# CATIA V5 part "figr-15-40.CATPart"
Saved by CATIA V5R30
Part number: Part1
Bounding box of the stored display mesh (mm): x -55.204 to 69.266, y -33.79 to 44.107, z 0 to 118.408
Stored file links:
  D:\PROJECTS\CATIA V56R 2020\Resources\Parts File\c15_catia_v5_6r2020_prt\figr-15-40.CATPart
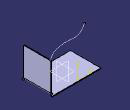
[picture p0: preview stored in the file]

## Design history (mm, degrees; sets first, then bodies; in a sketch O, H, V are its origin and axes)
SheetMetalParameters1: Thickness 2, BendRadius 4, KFactor 0.400515 {= log(min(100,max(20*SheetMetalParameters1.BendRadius,SheetMetalParameters1.Thickness)/SheetMetalParameters1.Thickness))/log(100)/2}, ReliefRadialLength 1, ReliefAxialLength 2, MinimumBendRadius 0
Body1 (main body)
  Sketch1 on xy-plane, origin (0, 0, 0), H (1, 0, 0), V (0, 1, 0)
    line L1 (-55.2037, 44.1067) -> (69.266, 44.1067)
    line L2 (69.266, 44.1067) -> (69.266, -33.7896)
    line L3 (69.266, -33.7896) -> (-55.2037, -33.7896)
    line L4 (-55.2037, -33.7896) -> (-55.2037, 44.1067)
    horizontal: L1 H, L3 H
    vertical: L2 V, L4 V
  Wall1: Thickness 2, Profile Sketch1, OffsetValue 0
  d_NewWallOnEdge1: NewWallOnEdge_Length 77.8964, NewWallOnEdge_HeightLimitOffset 0, NewWallOnEdge_WidthOffset1 -4, NewWallOnEdge_WidthOffset2 -4, NewWallOnEdge_Angle 90, NewWallOnEdge_BendRadiusValue 4 {= SheetMetalParameters1.BendRadius}, NewWallOnEdge_BendTable SheetMetalParameters1, NewWallOnEdge_Edge edge [face of Wall1 | face of Wall1], NewWallOnEdge_GapValue 0, KFacteur 0.400515 {= log(min(100,max(20*d_NewWallOnEdge1.Radius,SheetMetalParameters1.Thickness)/SheetMetalParameters1.Thickness))/log(100)/2}
  Sketch2 on face of d_NewWallOnEdge1, origin (0, 40.1067, 0), H (-1, 0, 0), V (0, 0, 1)
    spline S1 through (-69.266, 77.8964) (-67.9767, 84.9607) (-48.7678, 98.5965) (6.1586, 103.3856) (17.3621, 118.4076)
    reference projected line E1 (-69.266, 6) -> (-69.266, 77.8964) from edge [face of d_NewWallOnEdge1 | face of d_NewWallOnEdge1]
    reference projected line E2 (-69.266, 6) -> (-69.266, 77.8964) from edge [face of d_NewWallOnEdge1 | face of d_NewWallOnEdge1]
    reference projected point E3 (-69.266, 77.8964) from vertex [face of d_NewWallOnEdge1 | face of d_NewWallOnEdge1 | face of d_NewWallOnEdge1]
    point P1 (-69.266, 77.8964)
    coincidence: P1 E1, P1 E3
    tangency: S1 E2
